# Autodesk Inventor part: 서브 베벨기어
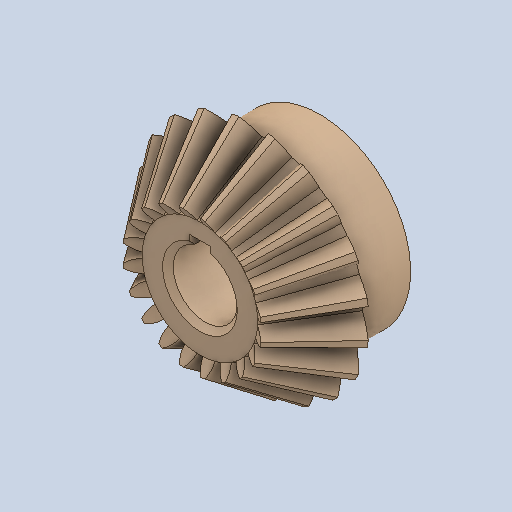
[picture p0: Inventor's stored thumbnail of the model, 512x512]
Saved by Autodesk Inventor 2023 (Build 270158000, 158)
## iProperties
Created: 2025-04
Part Number: 서브 베벨기어
Material: 강철, 탄소
Document SubType Name: Modeling
Designer: Admin
Density: 7.87 g/cm^3
Appearance: 기본값
Author: jhkim
Revision Number: 1
Sending System: Autodesk Inventor 2026
Preprocessor: ST-DEVELOPER v20.1
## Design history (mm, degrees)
node "복구된 형상1"
  node "스케치11"
feature "Solid1"
node "스케치10"
node "솔리드1"
